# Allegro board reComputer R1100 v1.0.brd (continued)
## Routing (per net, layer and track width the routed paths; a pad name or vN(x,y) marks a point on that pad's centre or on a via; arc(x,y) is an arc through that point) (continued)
GND_ISO: length 151.2
  TOP w1.016: J23.5 98.62,20.46 R165.1 97.77,19.8 v1(92.81,14.85) v1(92.38,14.41) v1(91.95,13.98) v1(91.52,13.55)
  LYR2_GND w0.375: J21.6 81.09,8.56 ; J21.6 79.83,7.3 ; J21.6 81.09,6.04 ; J21.6 82.34,7.3 ; 102.69,7.3 J21.18 ; J21.18 103.95,8.56 ; J21.18 103.95,6.04 ; J21.18 105.2,7.3 ; 103.95,9.54 J21.17 ; J21.17 105.2,10.8 ; J21.17 102.69,10.8 ; J21.17 103.95,12.06 ; J21.5 81.09,12.06 ; J21.5 81.09,9.54 ; J21.5 79.83,10.8 ; J21.5 82.34,10.8 ; 59.04,19.26 U22.3 59.75,18.3
  LYR3 w0.375: 81.09,6.04 J21.6 ; J21.6 81.09,8.56 ; J21.6 82.34,7.3 ; J21.6 79.83,7.3 ; 59.04,19.26 U22.3 59.75,18.3 ; 81.09,9.54 J21.5 ; J21.5 79.83,10.8 ; J21.5 82.34,10.8 ; J21.5 81.09,12.06 ; J21.17 105.2,10.8 ; J21.17 103.95,9.54 ; J21.17 102.69,10.8 ; J21.17 103.95,12.06 ; J21.18 103.95,8.56 ; J21.18 102.69,7.3 ; J21.18 105.2,7.3 ; J21.18 103.95,6.04
  LYR4_GND w0.375: 103.95,9.54 J21.17 ; J21.17 105.2,10.8 ; J21.17 103.95,12.06 ; J21.17 102.69,10.8 ; 102.69,7.3 J21.18 ; J21.18 103.95,8.56 ; J21.18 103.95,6.04 ; J21.18 105.2,7.3 ; 79.83,7.3 J21.6 ; J21.6 82.34,7.3 ; J21.6 81.09,6.04 ; J21.6 81.09,8.56 ; 59.75,18.3 U22.3 59.04,19.26 ; 81.09,9.54 J21.5 ; J21.5 81.09,12.06 ; J21.5 82.34,10.8 ; J21.5 79.83,10.8
  LYR5_PWR w0.375: 79.83,10.8 J21.5 ; J21.5 81.09,12.06 ; J21.5 82.34,10.8 ; J21.5 81.09,9.54 ; J21.6 82.34,7.3 ; J21.6 81.09,6.04 ; J21.6 81.09,8.56 ; J21.6 79.83,7.3 ; 103.95,9.54 J21.17 ; J21.17 102.69,10.8 ; J21.17 105.2,10.8 ; J21.17 103.95,12.06 ; 102.69,7.3 J21.18 ; J21.18 103.95,8.56 ; J21.18 105.2,7.3 ; J21.18 103.95,6.04 ; 59.04,19.26 U22.3 59.75,18.3
  LYR6 w0.375: 102.69,7.3 J21.18 ; J21.18 103.95,6.04 ; J21.18 105.2,7.3 ; J21.18 103.95,8.56 ; 79.83,7.3 J21.6 ; J21.6 81.09,6.04 ; J21.6 82.34,7.3 ; J21.6 81.09,8.56 ; J21.17 103.95,12.06 ; J21.17 102.69,10.8 ; J21.17 103.95,9.54 ; J21.17 105.2,10.8 ; J21.5 82.34,10.8 ; J21.5 79.83,10.8 ; J21.5 81.09,9.54 ; J21.5 81.09,12.06
  LYR7_GND w0.375: 79.83,10.8 J21.5 ; J21.5 81.09,9.54 ; J21.5 81.09,12.06 ; J21.5 82.34,10.8 ; J21.18 103.95,8.56 ; J21.18 105.2,7.3 ; J21.18 103.95,6.04 ; J21.18 102.69,7.3 ; 103.95,9.54 J21.17 ; J21.17 103.95,12.06 ; J21.17 102.69,10.8 ; J21.17 105.2,10.8 ; 59.04,19.26 U22.3 59.75,18.3 ; J21.6 82.34,7.3 ; J21.6 81.09,6.04 ; J21.6 79.83,7.3 ; J21.6 81.09,8.56
  BOTTOM w1.524: C134.2 78.87,15.61 D34.1 81.09,13.4 J21.5 J21.6
  vias: v1(57.69,21.93) v1(57.71,21.47) v1(57.71,21.02) v1(57.69,20.56)
GND_ISO_DI: length 11
  BOTTOM w1.016: J21.11 92.52,13.11 94.81,15.4 J20.1 J20.2 100.24,15.4
V3: length 2.2
  TOP w0.254: U15.6 36.64,51.47 C101.2 R91.2
VCC_USB1:
  vias: v1(98.45,54.52) v1(98.45,54.06) v1(98.99,54.52) v1(99.01,54.06) v1(108.94,74.99) v1(108.94,74.56) v1(109.37,74.99) v1(109.37,74.56)
VCC_USB2:
  vias: v1(101.35,52.62) v1(101.35,52.18) v1(101.86,52.62) v1(101.86,52.18) v1(111.91,70.45) v1(111.94,70.01) v1(112.37,70.45) v1(112.4,70.01)
VDD18CORE: length 20.7
  TOP w0.254: C14.1 44.95,34.06 v1(45.53,33.48) U4.38 ; U4.15 57.28,35.48 C19.1 58.47,36.09 C6.1 v1(58.77,36.83)
  LYR6 w0.305: v1(45.53,33.48) 46.97,34.91 56.85,34.91 v1(58.77,36.83)
VDD18ETHPLL: length 3.3
  TOP w0.254: FB3.1 43.36,28.14 C502.1 44.67,28.48 U4.48
VDD18USBPLL: length 14.2
  TOP w0.254: v1(52.96,28.76) 53.34,28.39 U4.62
  TOP w0.305: FB3.2 C501.1 43.41,25.26 43.72,25.56 v1(43.72,25.74)
  LYR6 w0.381: v1(52.96,28.76) 52.33,29.4 47.37,29.4 v1(43.72,25.74)
VDD33_HUB1: length 51.7
  TOP w0.254: C46.1 44.85,32.75 44.34,32.24 R43.1 ; C46.1 44.91,32.98 U4.39 ; C46.1 v1(44.85,33.49) ; v1(50.75,25.39) 50.68,25.46 R78.1 ; U4.27 49.34,37.16 48.48,38.02 46.97,38.02 v1(46.81,38.18) ; v1(44.83,29.93) 44.85,29.91 C45.1 44.93,29.48 U4.46 ; C41.1 44.79,35.98 U4.33 ; R41.1 57.25,33.77 57.98,33.05 R44.1 v1(58.24,32.68) ; R81.1 48.04,25.39 v1(47.91,25.26) ; C47.1 56.44,36.6 v1(56.37,36.68) 56.37,36.86 55.83,37.39 53.57,37.39 53.34,37.16 U4.19 ; v1(49.13,25.28) 49,25.41 R80.1 R79.1
  LYR6 w0.381: v1(47.91,25.26) 49.1,25.26 v1(49.13,25.28) 50.65,25.28 v1(50.75,25.39) 50.75,25.13 51.26,24.62 56.42,24.62 58.85,27.06 v1(58.85,28.82)
  BOTTOM w0.203: C40.1 46.54,38.01 46.01,37.49 R50.2
  BOTTOM w0.254: C40.1 v1(46.81,38.18)
  BOTTOM w0.305: v1(44.07,36.26) 43.82,36 43.81,36 42.48,36 40.54,37.93 29.77,37.93 28.72,36.88 C500.1 28.73,36.65 U33.8
  vias: v1(44.07,36.71) v1(44.5,36.71) v1(44.5,36.26) v1(58.42,28.82)
VDD33_HUB2: length 102.9
  TOP w0.254: v1(77.11,74.63) 77.9,73.84 v1(77.9,68.54) ; U4.40 v1(46.81,32.48)
  TOP w0.305: v1(97.26,74.43) R66.2 R61.2 R67.2 R62.2 R68.2 ; U5.5 v1(102.36,69.45) ; C64.1 94.82,65.85 v1(94.8,65.87) 94.13,66.53 94.13,69.02 94.57,69.45 U5.23 ; C63.1 96.88,65.54 v1(96.9,65.57) U5.29 ; U5.10 v1(100.4,72.95) ; v1(100.51,65.87) 100.51,66.2 100.4,66.31 U5.36 ; R65.2 R60.2 98.69,74.06 98.18,73.55 C67.1 97.92,73.22 v1(97.9,73.21) U5.15
  LYR3 w0.254: v1(48.69,65.34) 48.69,52.29 52.71,48.27 52.71,36.26 51.39,34.94 47.75,34.94 46.84,34.02 46.81,34.02 v1(46.81,32.48)
  BOTTOM w0.254: v1(77.9,68.54) 77.42,68.06 62.72,68.06 62.36,67.7 49.91,67.7 48.69,66.48 v1(48.69,65.34)
  BOTTOM w0.305: v1(83.19,74.08) R52.1 R59.1 ; R63.2 86.58,74.48 C73.1 v1(86.07,74.49) ; R51.1 76.57,74.09 v1(77.11,74.63) C68.1 U6.4 ; C65.1 v1(102.36,69.45) ; C62.1 100.4,71.89 v1(100.4,72.95) ; v1(100.51,65.87) 100.54,65.9 100.61,65.9 100.97,66.26 C66.1
  vias: v1(101.37,73.16) v1(101.81,73.16) v1(102.24,73.16)
VDD33A_HUB1: length 10.5
  TOP w0.254: v1(51.49,25.23) 51.33,25.39 51.33,25.59 C50.1 51.33,26.23 50.84,26.72 U4.57 ; U4.51 v1(47.84,28.47) ; C54.1 v1(56.42,30.5) 56.39,30.48 U4.5 ; v1(45.44,25.79) 45.87,26.22 C53.1 46.21,26.56 46.84,27.19 U4.49 ; U4.54 v1(49.34,28.56) ; 56.46,26.19 C52.1 ; U4.10 v1(56.36,32.98) 56.43,33.04 C51.1
  vias: v1(56.9,28.66) v1(57.33,28.71)
VDD_3.3V: length 29.7
  BOTTOM w0.203: C4.1 71.12,25.21
  BOTTOM w0.508: FB15.2 77.78,22.9 80.06,25.18 R164.1 ; 71.12,25.21 71.07,25.26
  BOTTOM w1.016: FB15.2 74.83,22.9 72.47,25.26 67.59,25.26 65.36,23.02 J17.2
VDD_3V3_PCIE: length 11.3
  LYR6 w0.381: v1(24.89,48.32) 19.28,48.32 v1(18.7,48.91)
  BOTTOM w0.254: C168.1 25.01,47.93 25.53,47.41 R175.1
  BOTTOM w0.305: OSC1.1 OSC1.4 23.73,47.93 C168.1 v1(24.89,48.32)
  vias: v1(17.76,49.34) v1(18.21,49.34) v1(18.21,48.91) v1(18.7,49.34) v1(19.46,69.84) v1(19.46,69.4) v1(19.46,68.97) v1(19.46,67.19) v1(19.46,66.76) v1(19.46,66.33) v1(19.46,65.9)
VDD_3V3_SYS: length 68.9
  TOP w0.203: U3.9 60.28,28.27 C38.1
  TOP w0.254: 36.98,63.39 C508.1 v1(36.67,64.01) ; 36.98,63.39 37.18,63.19 U20.7 ; 36.98,63.39 36.68,63.09 U20.8 ; v1(66.04,36.64) 66.04,36.59 65.83,36.37 R654.1 ; U19.8 v1(33.65,70.13)
  TOP w0.305: v1(33.65,70.13) 33.63,70.11 C110.2 ; v1(61.04,28.43) 61.04,28.29 60.73,27.99 C38.1 ; R128.1 v1(17.61,63.79) ; R85.1 R88.1 R89.1 24.98,72.14 24.48,71.63 24.48,70.37 ; v1(16.94,62.32) 17.11,62.15 R127.1 ; R124.1 17.11,54.27 v1(17.11,55.35) R125.1 ; R126.1 v1(17.11,58.75) ; v1(18.01,66.43) 17.65,66.43 R86.1
  TOP w0.381: 16.12,51.69 C129.2 v1(16.33,50.99) v1(16.33,50.56)
  TOP w0.508: D27.1 v1(10.51,75.99) ; 16.12,51.69 D40.2 13.57,52.39 13.06,52.9 13.06,57.44 13.49,57.87 J26.4
  LYR6 w0.305: v1(46.61,39.53) 49.38,39.53 50.57,40.73 58.7,40.73 61.39,43.42 v1(61.39,44.72)
  BOTTOM w0.254: U24.8 76.58,19.85 76.84,20.1 ; 61.27,47.31 61.39,47.18 v1(61.39,44.72) ; 76.84,20.1 76.81,20.1 76.57,20.35 U24.7 ; 76.84,20.1 C509.1
  BOTTOM w0.305: C30.1 46.93,39.22 v1(46.61,39.53) 46.15,39.99 R653.1 ; R102.1 60.12,79.4 60.63,79.91 C107.1 v1(60.63,80.43) 60.63,81.06 60.95,81.38 U17.8 ; C106.1 v1(16.85,20.28)
  BOTTOM w0.381: v1(40.57,29.25) 40.14,29.68 D25.1 ; C509.1 77.27,20.1 v1(78.06,20.89)
  BOTTOM w0.508: FB9.1 35,18.83 v1(34.95,18.78) ; R38.1 v1(16.77,76.49)
  BOTTOM w0.635: J13.7 17.35,15.02 17.91,15.58 17.91,18.22 17.3,18.83 J13.1
  vias: v1(13.06,46.85) v1(13.06,46.39) v1(13.49,46.85) v1(13.49,46.39) v1(13.92,46.85) v1(13.92,46.39) v1(15.78,5.9) v1(15.78,5.42) v1(17.27,20.28) v1(23.37,70.73) v1(23.83,70.7) v1(40.54,28.82) v1(41.07,29.25) v1(41.07,28.82) v1(42.9,31.97) v1(42.9,31.53) v1(43.33,31.97) v1(43.33,31.53) v1(60.89,49.58) v1(60.89,49.1) v1(60.89,48.67) v1(60.89,48.21) v1(61.34,49.58) v1(61.34,49.1) v1(61.34,48.67) v1(61.34,48.21) v1(64.52,27.55) v1(64.52,27.11) v1(75.01,25.6) v1(75.01,25.14) v1(75.44,25.6) v1(75.44,25.14) v1(103.02,75.53) v1(103.02,75.09) v1(103.28,74.71) v1(103.79,74.71)
VDD_5V_SYS: length 32.8
  LYR6 w0.305: v1(64.75,37.88) 65.05,38.19 70.67,38.19 73,40.52 76.94,40.52 81.13,44.72 v1(81.13,47.89)
  BOTTOM w0.254: 9.73,36.41 9.72,36.4 R33.2
  BOTTOM w0.305: R104.1 11.26,72.83 R105.1 13.9,72.71 14.33,72.27 16.41,72.27 16.88,72.74 U18.5 17.61,72.74 17.88,73 C108.1 v1(18.44,73) ; C17.1 63.89,38.49 R652.1 63.9,38.43 64.42,37.91 64.62,37.91 64.72,37.91 v1(64.75,37.88)
  vias: v1(5.62,38.82) v1(5.62,38.32) v1(6.12,38.82) v1(6.12,38.32) v1(17.05,73.34) v1(17.5,73.37) v1(52.02,78.14) v1(52.02,77.71) v1(52.02,77.28) v1(52.45,78.14) v1(52.45,77.71) v1(52.45,77.28) v1(52.89,78.14) v1(52.89,77.71) v1(76.84,24.57) v1(77.27,24.57) v1(77.7,24.57) v1(80.62,49.29) v1(80.62,48.83) v1(80.62,48.35) v1(80.65,47.89) v1(80.93,67.55) v1(80.95,67.07) v1(81.13,49.29) v1(81.13,48.83) v1(81.13,48.35) v1(81.38,67.55) v1(81.41,67.07) v1(81.84,67.55) v1(81.87,67.07) v1(82.2,56.43) v1(82.2,55.92) v1(82.3,67.55) v1(82.32,67.07) v1(82.7,56.4) v1(82.7,55.89) v1(83.21,56.43) v1(83.21,55.92) v1(83.67,56.43) v1(83.67,55.92) v1(100.1,52.62) v1(100.1,52.18) v1(100.61,52.62) v1(100.61,52.18) v1(108.51,72.83) v1(108.51,72.33) v1(108.99,72.83) v1(108.99,72.33)
VDD_IN:
  vias: v1(17.53,81.09) v1(18.04,81.09) v1(18.52,81.06) v1(18.52,80.56) v1(32.01,78.27) v1(31.98,77.79) v1(31.98,77.28) v1(42.45,53.58) v1(42.9,54.06) v1(42.9,53.58) v1(61.62,40.4) v1(61.62,39.94) v1(61.62,39.48) v1(62.05,40.4) v1(62.05,39.94) v1(62.05,39.48) v1(62.49,40.4) v1(62.49,39.94) v1(62.49,39.48) v1(64.09,53.56) v1(64.59,53.56) v1(70.59,30.36) v1(70.59,29.91) v1(70.59,29.45) v1(70.59,28.99) v1(71.05,30.36) v1(71.05,29.91) v1(71.05,29.45) v1(71.05,28.99) v1(82.25,38.77) v1(82.25,38.32) v1(82.25,37.86) v1(82.68,38.77) v1(82.68,38.32) v1(82.68,37.86) v1(83.11,38.77) v1(83.11,38.32) v1(83.11,37.86)
VDD_LTE_3V3: length 7
  BOTTOM w0.305: TP31.1 110.19,33.06 109.5,32.37 107.65,32.37 107.37,32.65 v1(107.37,33.31)
  BOTTOM w0.381: J15.41 v1(84.55,28.69) ; J15.39 v1(85.35,28.69)
  vias: v1(74.42,75.75) v1(74.98,75.75) v1(79.53,35.29) v1(79.53,34.86) v1(79.53,34.43) v1(79.53,34) v1(106.83,33.82) v1(106.83,33.31) v1(107.37,33.82)
VDD_RTC: length 11.8
  TOP w0.305: 14.15,74.03 14.19,74.07 C105.1 13.85,74.39 13.84,74.38
  TOP w0.508: 14.15,74.03 14.15,72.81 14.66,72.3 U16.8 ; v1(13.83,78.1) D29.2 D27.2 12.77,76.71 12.15,76.09 D28.2 12.15,74.38 C104.1 13.84,74.38
  BOTTOM w0.508: TP22.1 13.58,78.1 v1(13.83,78.1)
VDD_UPS: length 10.2
  BOTTOM w0.508: 85.42,45.9 84.15,44.63 Q1.5 ; 85.42,45.9 Q1.6 ; 85.42,45.9 Q1.9 85.42,47.17 ; 85.42,47.17 84.15,48.44 Q1.8 ; 85.42,47.17 Q1.7
  vias: v1(82.68,43.12) v1(82.68,42.66) v1(82.68,42.2) v1(82.68,41.72) v1(83.14,43.12) v1(83.14,42.66) v1(83.14,42.2) v1(83.14,41.72)
BUZZER_EN: length 9.7
  TOP w0.121: v1(32.01,72.15) 32.01,71.74 31.62,71.36 U12.11
  LYR6 w0.121: v1(32.01,72.15) 31.5,72.66 v1(25.1,72.66)
  BOTTOM w0.121: v1(25.1,72.66) 24.62,73.14 R39.1
CAM0_C_N: length 76.2
  TOP w0.095: J5.140 66.14,38.81 66.14,40.21 65.75,40.6 65.15,40.6 v1(65.04,40.72)
  LYR6 w0.102: v1(65.04,40.72) 65.14,40.61 65.6,40.61 65.99,41 65.99,43.14 63.83,45.3 50.9,45.3 47.62,48.58 28.35,48.58 24.56,52.36 13.34,52.36 9.99,55.71 9.99,58.36 10.27,58.64 10.78,58.64 10.88,58.74 v1(10.88,59.03)
  BOTTOM w0.095: D58.2 10.92,59.07 v1(10.88,59.03) 10.76,58.91 9.77,58.91 9.65,59.04 J24.8
CAM0_C_P: length 76.4
  TOP w0.095: v1(65.04,40.21) 65.15,40.32 65.64,40.32 65.86,40.1 65.86,39.93 65.77,39.84 65.6,39.84 65.51,39.74 65.51,39.55 65.6,39.46 65.77,39.46 65.86,39.36 65.86,38.81 J5.142
  LYR6 w0.102: v1(65.04,40.21) 65.14,40.31 65.73,40.31 66.3,40.88 66.3,43.27 63.96,45.6 51.03,45.6 47.75,48.88 28.48,48.88 24.69,52.67 13.46,52.67 10.29,55.84 10.29,58.23 10.4,58.34 10.78,58.34 10.88,58.24 10.88,57.95 v1(10.91,57.95)
  BOTTOM w0.095: D59.2 10.93,57.93 v1(10.91,57.95) 10.23,58.64 9.92,58.64 9.77,58.49 9.77,58.25 9.54,58.03 8.19,58.03 8.04,58.18 8.04,58.44 8.14,58.54 J24.9
CAM0_D0_N: length 87.3
  TOP w0.095: J5.128 68.54,38.81 68.54,39.68 68.18,40.03 v1(68.18,40.2)
  LYR6 w0.102: v1(68.18,40.2) 68.18,40.05 68.4,39.84 68.73,39.84 68.84,39.94 68.84,41.72 68.05,42.51 68.05,44.31 65.33,47.03 52,47.03 46.87,52.16 35.79,52.16 35.17,51.54 28.56,51.54 25.57,54.53 19.73,54.53 19.63,54.43 19.63,54.29 19.53,54.19 19.32,54.19 19.22,54.29 19.22,54.43 19.12,54.53 18.92,54.53 18.82,54.43 18.82,54.34 18.71,54.24 18.51,54.24 18.41,54.34 18.41,54.43 18.31,54.53 18.1,54.53 18,54.43 18,54.34 17.9,54.24 17.7,54.24 17.6,54.34 17.6,54.43 17.5,54.53 17.29,54.53 17.19,54.43 17.19,54.34 17.09,54.24 16.89,54.24 16.78,54.34 16.78,54.43 16.68,54.53 16.48,54.53 16.38,54.43 16.38,54.34 16.28,54.24 16.07,54.24 15.97,54.34 15.97,54.43 15.87,54.53 15.67,54.53 15.56,54.43 15.56,54.34 15.46,54.24 15.26,54.24 15.16,54.34 15.16,54.43 15.06,54.53 14.59,54.53 13.1,56.03 13.1,62.48 11.15,64.43 10.54,64.43 10.26,64.15 10.26,63.05 10.44,62.88 10.71,62.88 10.81,62.98 v1(10.81,63.28)
  BOTTOM w0.095: J24.2 6.57,62.04 9.57,62.04 v1(10.81,63.28) 10.84,63.31 D53.2
CAM0_D0_P: length 87.2
  TOP w0.095: J5.130 68.26,38.81 68.26,39.56 67.99,39.84 v1(67.83,39.84)
  LYR6 w0.102: v1(10.81,62.17) 10.81,62.47 10.71,62.57 10.32,62.57 9.96,62.93 9.96,64.27 10.42,64.73 11.28,64.73 13.4,62.61 13.4,56.16 14.72,54.84 25.69,54.84 28.69,51.84 35.04,51.84 35.66,52.46 46.99,52.46 52.12,47.33 65.46,47.33 68.35,44.44 68.35,42.63 69.14,41.85 69.14,39.81 68.86,39.53 68.27,39.53 67.97,39.84 v1(67.83,39.84)
  BOTTOM w0.095: D55.2 10.82,62.17 v1(10.81,62.17) 10.6,62.38 10.3,62.38 9.74,61.82 9.74,61.28 9.48,61.02 8.16,61.02 8.07,61.12 8.07,61.44 8.16,61.54 J24.3
CAM0_D1_N: length 77
  TOP w0.095: J5.134 67.4,39.31 67.34,39.37 67.34,40.28 v1(67.46,40.4)
  LYR6 w0.102: v1(67.46,40.4) 67.35,40.5 67.35,43.76 64.62,46.49 51.39,46.49 46.39,51.5 36.3,51.5 35.51,50.71 28.22,50.71 25.22,53.71 14.25,53.71 11.79,56.17 11.79,60.48 11.51,60.76 10.94,60.76 10.84,60.86 v1(10.84,61.15)
  BOTTOM w0.095: D56.2 10.87,61.18 v1(10.84,61.15) 10.84,60.57 10.72,60.45 10.52,60.45 10.4,60.57 10.4,61.22 10.29,61.33 10.15,61.33 10.05,61.23 10.05,60.51 9.95,60.41 9.74,60.41 9.62,60.54 J24.5
CAM0_D1_P: length 77.1
  TOP w0.095: v1(66.95,40.4) 67.06,40.28 67.06,39.37 67,39.31 J5.136
  LYR6 w0.102: v1(66.95,40.4) 67.05,40.5 67.05,43.63 64.49,46.19 51.27,46.19 46.26,51.19 36.43,51.19 35.64,50.41 28.09,50.41 25.1,53.4 17.49,53.4 17.33,53.25 17.08,53.25 16.93,53.4 16.67,53.4 16.52,53.25 16.27,53.25 16.12,53.4 15.86,53.4 15.71,53.25 15.45,53.25 15.3,53.4 15.05,53.4 14.9,53.25 14.64,53.25 14.49,53.4 14.12,53.4 11.48,56.04 11.48,60.35 11.38,60.45 10.94,60.45 10.84,60.35 v1(10.84,60.06)
  BOTTOM w0.095: D57.2 10.85,60.04 v1(10.84,60.06) 10.8,60.02 10.56,60.02 10.44,60.13 9.74,60.13 9.65,60.04 J24.6
CAM_GPIO: length 80
  TOP w0.121: J4.97 54.6,75.21 54.49,75.09 49.96,75.09 45.27,70.4 41.02,70.4 v1(39.52,71.89)
  LYR6 w0.121: v1(39.52,71.89) 35.27,76.15 24.09,76.15 23.95,76.29 21.82,76.29 19.69,74.15 16.87,74.15 16.18,73.47 16.18,69.35 16.06,69.23 11.58,69.23 5.16,62.8 v1(5.16,55.54)
  BOTTOM w0.121: J24.17 D64.2 11.37,55.65 10.98,56.04 7.93,56.04 7.42,55.54 v1(5.16,55.54)
CH344_RST: length 101.2
  TOP w0.121: v1(29.44,73.39) 29.68,73.16 U12.15 ; J22.2 70.86,15.63 v1(67.77,15.63)
  LYR3 w0.121: v1(29.44,73.39) 29.44,71.41 28.73,70.7 28.73,62.5 27.18,60.95 27.18,56.5 26.34,55.66 26.34,49.14 24.82,47.61 24.82,39 27.74,36.08 27.74,30.34 v1(29.87,28.21)
  LYR6 w0.121: v1(29.87,28.21) 31.45,28.21 32.9,26.76 39.32,26.76 41.43,24.65 47.88,24.65 50.07,22.47 56.59,22.47 59.18,25.06 62.37,25.06 62.49,24.94 62.49,24.01 63.4,23.1 63.4,20 v1(67.77,15.63)
CM4_GPIO16: length 74.1
  TOP w0.121: J4.29 v1(68.2,75.2)
  LYR3 w0.121: v1(66.96,17.54) 65.74,17.54 61.62,21.65 61.62,23.91 61.45,24.09 61.45,27.16 62.99,28.71 64.44,28.71 70.84,35.11 70.84,36.71 71.81,37.68 71.81,38.19 73.79,40.17 73.79,42.66 74.37,43.24 74.37,43.85 70.16,48.07 70.16,61.18 68.76,62.57 68.76,65.57 68.07,66.26 68.07,66.99 68.25,67.17 68.25,70.42 67.82,70.85 67.82,74.27 68.2,74.65 v1(68.2,75.2)
  BOTTOM w0.121: J17.8 65.15,15.4 66.96,17.21 v1(66.96,17.54)
CM4_GPIO17: length 70.4
  TOP w0.121: J4.50 v1(64.2,72.1)
  LYR3 w0.121: v1(71.07,66.23) 71.94,65.37 71.94,48.93 76.76,44.11 76.76,29.45 68.25,20.94 68.25,20.2 67.52,19.47 v1(67.52,17.79) ; v1(64.2,72.1) 64.2,68.83 65.28,67.75 65.28,67.58 v1(65.28,67.58)
  BOTTOM w0.121: v1(67.52,17.79) 67.52,16.78 68.89,15.4 J17.7 ; v1(71.07,66.23) 69.73,67.58 v1(65.28,67.58)
CM4_GPIO_VREF: length 43.6
  TOP w0.203: J4.78 v1(58.6,72.07)
  TOP w0.305: v1(61.34,80.71) 61.66,80.39 R106.1 R107.1 R178.1 R177.1 ; R30.1 R31.1 v1(35.76,68.74)
  LYR3 w0.305: v1(61.34,80.71) 61.34,80.35 59.54,78.55 v1(59.54,73.42)
  BOTTOM w0.305: C35.2 58.76,72.78 R29.1 ; C35.2 58.88,72.35 v1(58.6,72.07) 57.81,71.28 48.06,71.28 46.32,69.55 36.57,69.55 v1(35.76,68.74) ; C35.2 59.03,72.9 v1(59.54,73.42) 60.3,74.18 TP16.1
CM4_IIC0_SCL: length 96
  TOP w0.121: R177.2 66.84,79.66 v1(66.7,79.51) ; v1(67.36,76.49) 67,76.13 J4.35
  LYR3 w0.121: v1(67.36,76.49) 67,76.85 67,77.94 66.7,78.24 v1(66.7,79.51)
  LYR6 w0.121: v1(66.7,79.51) 66.7,79.37 65.65,78.32 59.09,78.32 58.35,77.58 54.41,77.58 51.47,74.64 50.7,74.64 45.65,69.58 38.66,69.58 33.86,74.38 24.25,74.38 21.54,71.67 18.45,71.67 18.04,71.26 18.04,68.9 17.5,68.36 11.79,68.36 5.97,62.55 5.97,54.29 6.86,53.4 10.43,53.4 v1(10.51,53.49)
  BOTTOM w0.121: D60.2 10.51,53.49 v1(10.51,53.49) 10.06,53.04 J24.20
CM4_IIC0_SDA: length 97.1
  TOP w0.121: J4.36 v1(67,73.29) ; R178.2 v1(66.08,79.32)
  LYR3 w0.121: v1(67,73.29) 67,74.24 66.27,74.97 66.27,77.99 66.08,78.18 v1(66.08,79.32)
  LYR6 w0.121: v1(66.08,79.32) 65.36,78.6 59.02,78.6 58.25,77.82 54.31,77.82 51.44,74.96 50.56,74.96 45.44,69.84 38.75,69.84 33.96,74.62 24.15,74.62 21.52,72 18.21,72 17.68,71.46 17.68,69.07 17.3,68.69 11.61,68.69 5.62,62.7 5.62,54.14 7.22,52.54 v1(10.55,52.54)
  BOTTOM w0.121: D54.2 10.62,52.47 v1(10.55,52.54) J24.21
CM4_IIC1_SCL: length 8.1
  TOP w0.121: R30.2 36.48,67.71 v1(36.63,67.71) 36.92,67.71 R27.1 ; v1(33.58,71.54) 33.99,71.13 U19.6
  LYR3 w0.121: v1(33.58,71.54) 34.03,71.09 34.03,69.1 35.43,67.71 v1(36.63,67.71)
CM4_IIC1_SDA: length 7
  TOP w0.121: U19.5 34.25,71.63 v1(34.04,71.84) ; R31.2 v1(36.61,68.3) R28.1
  LYR3 w0.121: v1(36.61,68.3) 35.28,68.3 34.5,69.07 34.5,71.39 v1(34.04,71.84)
CM4_IIC3_SCL: length 119.5
  TOP w0.121: v1(37.14,65.14) 37.13,65.15 R24.1 ; U12.19 27.47,71.86 v1(27.07,72.26) 26.5,72.83 R88.2 ; v1(69.73,18.99) 69.73,18.12 69.93,17.92 J22.4
  LYR3 w0.121: v1(27.05,65.14) 27.05,67.47 26.95,67.58 26.95,72.15 v1(27.07,72.26) ; v1(50.5,24.62) 50.12,25.01 50.12,32.42 50.51,32.81 53.86,32.81 57.28,36.23 v1(57.28,36.86) 56.81,36.86 56.37,37.3 56.37,52.01 55.65,52.72 55.65,66.1 v1(55.25,66.51)
  LYR6 w0.121: v1(50.5,24.62) 50.22,24.35 50.22,23.68 50.6,23.29 56.23,23.29 59.68,26.75 65.23,26.75 65.28,26.7 65.58,26.7 65.63,26.75 67.98,26.75 69.73,25.01 v1(69.73,18.99) ; v1(27.05,65.14) v1(37.14,65.14) 37.9,65.9 54.64,65.9 v1(55.25,66.51)
  BOTTOM w0.121: J14.30 56.84,36.42 v1(57.28,36.86)
CM4_IIC3_SDA: length 116.4
  TOP w0.121: J22.6 69.58,20.46 69.33,20.7 v1(69.33,21.37) ; U12.20 27.08,71.36 v1(26.55,71.89) 26.3,72.14 R89.2 ; v1(36.55,65.54) 36.55,66.13 R25.1
  LYR3 w0.121: v1(26.55,71.89) v1(26.55,65.54) ; v1(54.18,66.97) 55.4,65.75 55.4,52.62 56.11,51.9 56.11,37.07 55.76,36.71 v1(55.76,36.7) 55.76,35.34 53.67,33.26 50.32,33.26 49.74,32.68 49.74,25.16 49.08,24.5 v1(49.08,24.45)
  LYR6 w0.121: v1(69.33,21.37) 69.33,24.84 67.82,26.35 59.85,26.35 56.39,22.9 50.35,22.9 49.08,24.17 v1(49.08,24.45) ; v1(26.55,65.54) v1(36.55,65.54) 37.01,65.54 37.75,66.28 53.49,66.28 v1(54.18,66.97)
  BOTTOM w0.121: J14.32 56.04,36.42 v1(55.76,36.7)
CM4_IIC5_SCL: length 110.1
  TOP w0.121: U16.6 16.89,69.76 v1(16.94,69.81) ; v1(63.27,35.39) 63.6,35.06 J2.11 ; R6.1 v1(64.62,79.29) R106.2
  LYR3 w0.121: v1(64.62,79.29) 65,78.9 65,74.51 65.46,74.05 65.46,70.9 65.89,70.47 65.89,59.22 66.96,58.15 66.96,41.72 66.19,40.96 66.19,38.59 63.43,35.83 63.43,35.55 v1(63.27,35.39)
  LYR6 w0.121: v1(16.94,69.81) 16.94,72.05 17.5,72.61 21.14,72.61 23.65,75.12 34.17,75.12 38.92,70.37 45.09,70.37 50.35,75.63 51.41,75.63 54.1,78.32 58.04,78.32 59.01,79.29 v1(64.62,79.29)
  BOTTOM w0.121: U17.6 64.18,78.84 v1(64.62,79.29)
CM4_IIC5_SDA: length 116.1
  TOP w0.121: v1(17,69.18) 16.31,68.49 U16.5 ; R107.2 v1(65.38,79.31) R1.2 ; J2.13 62.33,35.17 v1(62.56,35.39)
  LYR3 w0.121: v1(65.38,79.31) 65.37,79.3 65.37,74.66 65.74,74.29 65.74,71.11 66.19,70.65 66.19,59.27 67.95,57.52 67.95,47.41 68.85,46.51 68.85,39.54 67.46,38.16 66.19,38.16 63.73,35.7 63.73,35.3 63.44,35 62.9,35 62.56,35.34 v1(62.56,35.39)
  LYR6 w0.121: v1(17,69.18) 17.38,69.56 17.38,71.74 17.96,72.33 21.29,72.33 23.83,74.87 34.07,74.87 38.85,70.09 45.24,70.09 50.39,75.24 51.37,75.24 54.21,78.07 58.14,78.07 58.97,78.89 64.97,78.89 v1(65.38,79.31)
  BOTTOM w0.121: v1(65.38,79.31) 63.64,77.57 U17.5
CM4_IN1: length 115.6
  TOP w0.121: v1(68.23,71.11) 68.23,68.72 67.8,68.29 62.38,68.29 62,68.67 57.31,68.67 56.47,67.82 56.47,66.38 55.66,65.57 54.25,65.57 53.18,66.64 49.26,66.64 48.37,65.75 41.38,65.75 40.64,65.01 40.64,59.09 39.78,58.23 37.42,58.23 37.18,58.47 U20.2 ; J4.49 64.2,75.44 64.39,75.25 v1(64.39,75.02)
  LYR3 w0.121: v1(70.41,71.11) 70.41,66.1 71.66,64.86 71.66,48.63 75.77,44.51 75.77,29.08 67.68,21 v1(67.68,20.43) ; v1(65.23,69.63) 65.23,70.62 64.59,71.26 64.59,74.81 v1(64.39,75.02)
  BOTTOM w0.121: v1(65.23,69.63) 67.03,69.63 67.31,69.91 67.31,70.67 67.74,71.11 v1(68.23,71.11) v1(70.41,71.11) ; v1(67.68,20.43) 69.76,20.43 J17.3
CM4_IN1_LED: length 94.6
  TOP w0.121: v1(16.65,3.02) J25.7 ; v1(35.69,62.63) 35.69,62.27 36.45,61.51 37.44,61.51 37.68,61.74 U20.6
  LYR3 w0.121: v1(16.65,3.02) 16.59,3.09 12.22,3.09 11.15,4.15 11.15,10.68 7.24,14.59 7.24,21.1 5.62,22.73 5.62,26.81 6.96,28.16 6.96,41.38 8.21,42.63 13.62,42.63 22.41,51.42 22.41,60.41 22.43,60.44 v1(22.43,61.56)
  BOTTOM w0.121: v1(35.69,62.63) 35.13,62.63 33.51,61 22.55,61 22.43,61.12 v1(22.43,61.56)
CM4_IN2: length 100.1
  TOP w0.121: J4.26 69,71.58 68.99,71.56 ; 68.99,71.56 v1(69.93,71.56) ; 68.99,71.56 68.02,71.56 67.07,70.61 67.07,69.19 66.55,68.67 62.54,68.67 62.16,69.05 57.15,69.05 56.09,67.98 56.09,66.53 55.5,65.95 54.41,65.95 53.34,67.02 49.1,67.02 48.21,66.13 39.96,66.13 38.18,64.35 U20.5
  LYR3 w0.121: v1(67.06,20.43) 67.06,20.95 75.36,29.25 75.36,44.39 71.29,48.46 71.29,64.61 69.93,65.98 v1(69.93,71.56)
  BOTTOM w0.121: v1(67.06,20.43) 64.44,20.43 J17.4
CM4_IN2_LED: length 94.1
  TOP w0.121: U20.3 37.68,61.04 37.57,61.15 36.25,61.15 34.89,62.51 v1(34.28,62.51) ; v1(17.65,3.02) J25.8
  LYR3 w0.121: v1(17.65,3.02) 17.16,3.52 12.5,3.52 11.97,4.05 11.97,10.58 7.74,14.8 7.74,21.3 6.11,22.93 6.11,26.6 7.46,27.95 7.46,41.18 8.42,42.14 13.83,42.14 22.99,51.3 22.99,59.65 23.29,59.96 v1(23.29,61.45)
  BOTTOM w0.121: v1(23.29,61.45) 33.23,61.45 v1(34.28,62.51)
CM4_IO_INT: length 52.6
  TOP w0.121: U12.22 27.06,70.36 26.77,70.06 R90.2 26.37,69.84 26.24,69.71 25.55,69.71 25.12,69.28 v1(25.12,64.1) ; J4.54 v1(63.4,69.35)
  BOTTOM w0.121: v1(63.4,69.35) 62.13,69.35 61.62,68.85 48.87,68.85 45.16,65.14 40.26,65.14 38.59,63.46 34.72,63.46 33.91,64.27 25.3,64.27 v1(25.12,64.1)
CM4_OUT1: length 73.8
  TOP w0.121: J4.27 v1(68.6,74.76)
  LYR3 w0.121: v1(68.6,74.76) 68.6,73.02 69.17,72.45 69.17,62.66 70.51,61.32 70.51,48.14 74.7,43.94 74.7,29.7 66.17,21.17 v1(66.17,18.96)
  BOTTOM w0.121: U24.2 73.95,20.35 74.07,20.23 74.07,19.57 72.44,17.94 J17.5 68.58,17.94 67.57,18.96 v1(66.17,18.96)
CM4_OUT1_LED: length 7.6
  TOP w0.121: J22.8 v1(73.08,23)
  BOTTOM w0.121: v1(73.08,23) 74.27,21.81 76.49,21.81 76.71,21.58 76.71,21.2 76.36,20.85 U24.6
CM4_OUT2: length 81.8
  TOP w0.121: J4.25 v1(69,75.18)
  LYR3 w0.121: v1(66.61,19.54) 66.61,21.09 74.96,29.45 75.03,29.52 75.03,44.08 70.84,48.27 70.84,61.45 69.5,62.8 69.5,72.33 70.28,73.11 70.28,73.42 69,74.7 v1(69,75.18)
  BOTTOM w0.121: v1(66.61,19.54) 64.92,19.54 64.39,19 J17.6 64.74,18.3 67.72,18.3 67.92,18.1 67.92,17.28 68.18,17.03 72.16,17.03 74.45,19.32 74.45,21.12 74.68,21.35 U24.5
CM4_OUT2_LED: length 7.3
  TOP w0.121: J22.10 71.11,24.31 71.4,24.01 v1(72.42,24.01)
  BOTTOM w0.121: U24.3 73.59,20.85 73.84,21.09 73.84,21.58 72.42,23 v1(72.42,24.01)
CM4_SDIO_CLK: length 56.7
  TOP w0.121: R129.1 v1(17.66,60.56) ; J4.46 v1(65,73.44)
  LYR6 w0.121: v1(17.66,60.56) 17.66,62.96 20.73,66.03 24.46,66.03 26.77,68.34 34.34,68.34 35.18,69.18 36.27,69.18 37.29,68.16 51.74,68.16 54.99,71.41 61.52,71.41 63.88,73.77 64.67,73.77 v1(65,73.44)
CM4_SDIO_CMD: length 68.8
  TOP w0.121: J26.3 15.56,56.77 D39.2 16.36,57.57 R126.2 v1(17.63,57.57) ; v1(60.09,77.1) 64.36,77.1 64.6,76.86 J4.47
  LYR6 w0.121: v1(28.65,73.98) 24.36,73.98 23.01,72.63 23.01,71.97 19.43,68.39 18.14,68.39 16.23,66.48 16.23,61.05 17.63,59.65 v1(17.63,57.57)
  BOTTOM w0.121: v1(60.09,77.1) 59.31,77.1 58.85,77.56 54.26,77.56 53.14,78.68 38.9,78.68 35.24,75.02 29.42,75.02 28.65,74.26 v1(28.65,73.98)
CM4_SDIO_DATA0: length 64.7
  TOP w0.121: v1(17.11,60.93) R127.2 16.77,61.38 16.56,61.17 D42.2 16.15,61.17 J26.7 ; J4.45 65,77.02 64.52,77.51 v1(60.56,77.51)
  LYR6 w0.121: v1(27.89,73.54) 27.46,73.11 24.44,73.11 23.7,72.38 23.7,71.65 19.73,67.68 18.43,67.68 17.17,66.42 17.17,63.23 17.33,63.08 17.33,61.14 v1(17.11,60.93)
  BOTTOM w0.121: v1(27.89,73.54) 27.89,74.07 29.25,75.42 35.07,75.42 38.73,79.08 53.31,79.08 54.43,77.96 59.02,77.96 59.48,77.51 v1(60.56,77.51)
CM4_SDIO_DATA1: length 64.8
  TOP w0.121: v1(60.1,77.91) 64.85,77.91 65.8,76.96 J4.41 ; J26.8 15.35,62.27 D43.2 16.36,63.28 R128.2 17.11,63.17 v1(16.74,62.8)
  LYR6 w0.121: v1(27.26,73.54) 24.34,73.54 23.37,72.58 23.37,71.82 19.59,68.03 18.29,68.03 16.74,66.48 v1(16.74,62.8)
  BOTTOM w0.121: v1(27.26,73.54) 27.26,74.01 29.08,75.83 34.9,75.83 38.56,79.49 53.48,79.49 54.59,78.37 59.19,78.37 59.65,77.91 v1(60.1,77.91)
CM4_SDIO_DATA2: length 69.3
  TOP w0.121: v1(18.37,55.23) 18.37,54.42 17.71,53.76 R124.2 16.36,53.76 D37.2 15.13,54.57 J26.1 ; J4.24 v1(69.4,73.29)
  LYR6 w0.121: v1(69.4,73.29) 69.34,73.29 68.56,72.5 63.93,72.5 62.05,70.62 55.32,70.62 52.07,67.37 37.29,67.37 36.91,66.99 33.25,66.99 32.77,67.47 27.13,67.47 24.82,65.16 20.93,65.16 18.37,62.6 v1(18.37,55.23)
CM4_SDIO_DATA3: length 62.4
  TOP w0.121: J26.2 15.44,55.67 D38.2 16.95,56.38 R125.2 17.26,56.07 v1(17.73,56.07) ; J4.48 64.6,73.03 64.26,73.37 v1(64.21,73.37)
  LYR6 w0.121: v1(17.73,56.07) 18.06,56.4 18.06,62.8 20.81,65.54 24.66,65.54 26.97,67.86 32.93,67.86 33.46,67.32 36.83,67.32 37.26,67.75 51.91,67.75 55.16,71 61.75,71 64.11,73.37 v1(64.21,73.37)
CM4_SPI0_CE0: length 106.7
  TOP w0.121: J4.39 66.2,74.42 65.92,74.13 50.12,74.13 49.51,73.52 v1(49.51,72.53)
  LYR3 w0.121: v1(39.42,20.13) 39.42,21.93 40.01,22.52 40.01,24.59 39.46,25.14 39.46,26.99 34.95,31.49 34.95,44.25 43.87,53.17 43.87,66.26 49.51,71.89 v1(49.51,72.53)
  LYR6 w0.121: v1(39.42,20.13) 35.66,20.13 34.78,19.24 32.11,19.24 28.5,15.63 22.28,15.63 v1(20.12,13.47)
  BOTTOM w0.121: J13.9 19.84,13.75 v1(20.12,13.47)
CM4_SPI0_CE1: length 82.8
  TOP w0.121: J4.37 66.6,74.41 66.07,73.88 53.48,73.88 v1(53.27,73.67)
  LYR3 w0.121: v1(53.27,73.67) 53.27,69.2 51.59,67.53 47.45,67.53 45.67,65.75 45.67,51.88 37.67,43.88 37.67,41.75 36.65,40.74 36.65,31.94 41.33,27.27 41.33,25.84 41.84,25.34 v1(41.94,25.34)
  BOTTOM w0.121: J14.51 48.44,25.97 48.26,25.79 46.33,25.79 45.87,25.34 v1(41.94,25.34)
CM4_SPI0_MISO: length 118.6
  TOP w0.121: J4.40 v1(66.2,72.1)
  LYR3 w0.121: v1(42.32,21.04) 42.32,24.32 41.05,25.59 41.05,27.2 36.4,31.84 36.4,40.84 37.39,41.83 37.39,43.96 45.39,51.96 45.39,65.82 47.4,67.83 51.31,67.83 52.83,69.35 52.83,70.75 v1(52.81,70.78)
  LYR6 w0.121: v1(42.32,21.04) 42.32,20.31 39.95,17.94 31.9,17.94 28.55,14.59 22.63,14.59 20.53,12.48 v1(19.03,12.48)
  BOTTOM w0.121: v1(52.81,70.78) 57.89,70.78 58.75,71.64 65.74,71.64 v1(66.2,72.1) ; v1(42.32,21.04) 42.32,22.85 44.02,24.55 48.47,24.55 48.81,24.89 49.36,24.89 50.04,25.58 J14.47 ; J13.11 v1(19.03,12.48)
CM4_SPI0_MOSI: length 121.1
  TOP w0.121: v1(64.62,70.62) 64.62,71.11 65.4,71.89 J4.44
  LYR3 w0.121: v1(52.28,69.66) 50.8,68.19 47.35,68.19 45.09,65.92 45.09,52.12 37.14,44.17 37.14,42.05 36.07,40.98 36.07,31.81 40.77,27.11 40.77,25.46 41.7,24.54 v1(41.7,21.04)
  LYR6 w0.121: v1(41.7,21.04) 41.7,20.19 39.8,18.3 31.65,18.3 28.48,15.12 22.48,15.12 20.42,13.07 v1(18.67,13.07)
  BOTTOM w0.121: v1(18.67,13.07) 13.69,13.07 13.11,12.48 J13.12 ; v1(41.7,21.04) 41.7,23.75 42.82,24.87 48.16,24.87 49.24,25.95 J14.49 ; v1(52.28,69.66) 52.38,69.76 58.24,69.76 59.11,70.62 v1(64.62,70.62)
CM4_SPI0_SCLK: length 120.6
  TOP w0.121: v1(66.47,71.16) 66.6,71.28 J4.38
  LYR3 w0.121: v1(41.28,20.64) 41.28,20.84 41.18,20.94 41.18,24.68 40.49,25.36 40.49,27.01 35.82,31.69 35.82,41.09 36.88,42.15 36.88,44.27 44.73,52.12 44.73,65.92 47.28,68.46 50.37,68.46 v1(51.56,69.66)
  LYR6 w0.121: v1(21.85,16.01) 28.43,16.01 32.06,19.65 34.72,19.65 35.71,20.64 v1(41.28,20.64)
  BOTTOM w0.121: v1(66.47,71.16) 59.16,71.16 58.09,70.09 52,70.09 v1(51.56,69.66) ; J13.10 13.52,13.75 14.1,14.34 20.17,14.34 v1(21.85,16.01) ; R111.1 47.36,23.62 46.81,24.17 44.2,24.17 42.95,22.92 42.95,21.02 42.57,20.64 v1(41.28,20.64)
CM4_TPM_IRQ: length 113.1
  TOP w0.121: v1(67.77,74.74) 67.77,74.1 67.4,73.74 J4.34
  LYR3 w0.121: v1(10.42,18.83) 10.42,20.03 7.11,23.33 7.11,26.19 7.86,26.93 7.86,26.95 8.45,27.54 8.45,37.34 9.35,38.24 12.25,38.24 13,38.99 13,39.88 24.38,51.26 24.38,66.26 v1(23.93,66.71)
  LYR6 w0.121: v1(23.93,66.71) 24.56,66.71 29.11,71.26 32.18,71.26 33.2,72.27 34.9,72.27 38.38,68.8 46.89,68.8 53.7,75.6 67.59,75.6 67.8,75.4 67.8,74.76 v1(67.77,74.74)
  BOTTOM w0.121: J13.2 v1(10.42,18.83)
CM4_UART0_RXD: length 48.6
  TOP w0.121: J4.51 63.8,75.15 v1(63.86,75.09) ; v1(33,54.37) 33.29,54.07 R100.2
  LYR3 w0.121: v1(34.98,60.9) 35.31,60.56 35.31,58.1 33,55.79 v1(33,54.37)
  LYR3 w0.127: v1(63.86,75.09) 63.8,75.04 63.8,67.53 v1(63.81,67.53)
  BOTTOM w0.121: v1(63.81,67.53) 63.35,67.07 56.82,67.07 54.13,64.38 40.89,64.38 37,60.49 35.41,60.49 35,60.9 v1(34.98,60.9)
CM4_UART0_TXD: length 50.9
  TOP w0.121: D26.2 32.45,52.34 v1(33.3,52.34) 33.53,52.56 R99.2 ; J4.55 v1(63,75.09)
  LYR3 w0.121: v1(33.3,52.34) 32.99,52.65 32.99,53.57 33.41,53.99 33.41,55.84 35.77,58.2 v1(35.77,60.9)
  LYR3 w0.127: v1(63,75.09) v1(63,67.53)
  BOTTOM w0.121: v1(63,67.53) 62.8,67.32 56.62,67.32 53.93,64.63 40.69,64.63 36.96,60.9 v1(35.77,60.9)
CM4_UPS_DET: length 51.9
  TOP w0.121: J4.30 68.2,72.15 v1(66.6,70.55) ; J2.12 63.08,29.45 61.65,30.87 61.65,35.14 62.56,36.05 64.62,36.05 v1(64.65,36.03) 64.69,35.99 R654.2
  LYR3 w0.121: v1(64.65,36.03) 66.4,37.78 67.57,37.78 69.12,39.33 69.12,46.77 68.35,47.54 68.35,57.64 66.5,59.5 66.5,67.4 66.6,67.5 v1(66.6,70.55)
EECLK: length 17.6
  TOP w0.121: U4.23 v1(51.34,37.27)
  LYR3 w0.121: v1(37.09,35.67) 37.44,35.67 38.08,36.31 40.77,36.31 41.86,37.4 46.28,37.4 46.76,36.92 50.98,36.92 v1(51.34,37.27)
  BOTTOM w0.121: v1(37.09,35.67) 36.79,35.38 U33.2
EECS: length 18.5
  TOP w0.121: v1(50.35,38.04) 50.35,37.96 50.84,37.47 U4.24
  LYR3 w0.121: v1(37.11,37.17) 37.16,37.17 37.77,36.56 40.66,36.56 41.8,37.71 45.01,37.71 45.85,38.54 47.76,38.54 48.69,37.6 49.91,37.6 v1(50.35,38.04)
  BOTTOM w0.121: v1(37.11,37.17) 36.99,37.05 R573.1 U33.1
EEDI: length 23.6
  TOP w0.121: v1(49.1,38.06) 49.1,38.01 49.84,37.27 U4.26
  LYR3 w0.121: v1(37.62,37.38) 37.62,37.27 38.05,36.84 40.54,36.84 41.68,37.98 44.94,37.98 45.75,38.8 48.36,38.8 v1(49.1,38.06)
  BOTTOM w0.121: v1(37.62,37.38) 37.43,37.56 34.96,37.56 34.14,36.74 34.14,33.08 34.38,32.84 U33.4
EEDO: length 23
  TOP w0.121: v1(49.71,38.04) 50.34,37.41 U4.25
  LYR3 w0.121: v1(49.71,38.04) 50.24,38.57 51.03,38.57 51.74,37.86 51.74,36.99 51.42,36.67 46.66,36.67 46.18,37.15 41.96,37.15 40.87,36.06 38.24,36.06 37.26,35.09 v1(37.11,35.09)
  BOTTOM w0.121: U33.3 36.44,34.11 36.68,34.35 36.68,34.66 v1(37.11,35.09)
EEPROM_WP: length 35.8
  TOP w0.121: U12.10 v1(32,70.86)
  BOTTOM w0.121: R103.2 60.63,78.19 61.01,77.81 61.01,77.1 60.48,76.57 59.44,76.57 58.78,77.23 53.09,77.23 52.58,76.72 50.95,76.72 49.84,75.6 49.84,73.98 46.13,70.27 35.26,70.27 34.67,70.86 v1(32,70.86)
ETHERNET_LED2: length 88.9
  TOP w0.121: J4.17 70.6,76.05 70.18,76.47 v1(68.3,76.47)
  LYR3 w0.121: v1(49.99,72.94) 49.99,72 44.15,66.15 44.15,52.46 36.32,44.64 36.32,42.3 35.21,41.18 35.21,31.59 39.72,27.08 39.72,25.35 40.41,24.65 40.41,22.41 39.83,21.83 39.83,20.41 v1(40.08,20.15)
  LYR6 w0.121: v1(68.3,76.47) 67.69,77.08 63.94,77.08 63.3,76.44 53.98,76.44 50.47,72.94 v1(49.99,72.94)
  BOTTOM w0.121: v1(40.08,20.15) 40.08,19.49 39.09,18.5 37.41,18.5 R155.1
ETHERNET_LED3: length 90
  TOP w0.121: J4.15 v1(71,75.2)
  LYR3 w0.121: v1(50.45,73.65) 50.45,72.02 44.4,65.98 44.4,52.26 36.63,44.49 36.63,42.25 35.49,41.11 35.49,31.66 40.13,27.01 40.13,25.31 40.69,24.75 40.69,22.29 40.44,22.03 40.44,20.54 v1(40.82,20.15)
  LYR6 w0.121: v1(50.45,73.65) 50.83,73.65 53.88,76.69 63.2,76.69 63.83,77.33 68.05,77.33 69.8,75.58 70.62,75.58 v1(71,75.2)
  BOTTOM w0.121: R160.1 39.61,17.98 40.82,19.19 v1(40.82,20.15)
ETHERNET_PAIR0_N: length 83.8
  TOP w0.095: v1(70.89,62.46) 71.11,62.46 71.23,62.57 71.68,62.57 72.14,63.03 72.14,72.05 72.2,72.11 J4.10
  BOTTOM w0.095: T1.3 15.92,38.06 15.83,38.15 15.44,38.15 15.34,38.25 15.34,38.44 15.44,38.54 15.83,38.54 15.92,38.63 15.92,38.84 16.03,38.95 U29.9 U29.2 16.03,40.78 15.91,40.89 15.91,41.24 16.04,41.37 16.04,41.72 15.91,41.85 15.91,42.21 16.04,42.33 16.04,42.69 15.91,42.82 15.91,43.53 16.98,44.59 17.33,44.59 17.46,44.47 17.81,44.47 17.94,44.59 18.3,44.59 18.42,44.47 18.78,44.47 18.91,44.59 24.81,44.59 33,52.78 33,53.18 34.24,54.42 37.71,54.42 44.9,61.61 54.31,61.61 57.48,64.78 62.68,64.78 64.89,62.57 70.56,62.57 70.68,62.46 v1(70.89,62.46)
ETHERNET_PAIR0_P: length 83.9
  TOP w0.095: v1(70.89,62.97) 71.11,62.97 71.23,62.85 71.57,62.85 71.86,63.15 71.86,63.5 71.74,63.63 71.74,63.99 71.86,64.11 71.86,64.47 71.74,64.6 71.74,64.95 71.86,65.08 71.86,65.43 71.74,65.56 71.74,65.92 71.86,66.04 71.86,66.64 71.74,66.76 71.74,67.12 71.86,67.25 71.86,72.05 71.8,72.11 J4.12
  BOTTOM w0.095: v1(70.89,62.97) 70.68,62.97 70.56,62.85 65,62.85 62.79,65.06 57.37,65.06 54.19,61.89 44.78,61.89 37.59,54.7 34.12,54.7 32.72,53.29 32.72,52.9 24.7,44.87 16.86,44.87 15.64,43.65 15.64,40.89 15.53,40.78 U29.1 U29.10 15.52,39.35 15.52,39.01 15.2,38.7 14.58,38.7 13.92,38.03 T1.1
ETHERNET_PAIR1_N: length 85
  TOP w0.095: J4.6 73,72.11 73.06,72.05 73.06,63.04 72.67,62.65 72.67,61.99 72.93,61.73 73.18,61.73 73.29,61.62 v1(73.51,61.62)
  BOTTOM w0.095: T1.6 18.92,38.17 18.47,38.62 17.75,38.62 17.53,38.85 U29.6 U29.5 17.53,40.78 17.42,40.89 17.42,41.24 17.54,41.37 17.54,41.72 17.42,41.85 17.42,42.27 17.54,42.39 17.54,42.75 17.42,42.88 17.42,43.23 17.81,43.62 18.16,43.62 18.29,43.5 18.65,43.5 18.77,43.62 19.43,43.62 19.56,43.5 19.92,43.5 20.04,43.62 25.58,43.62 34.83,52.87 37.51,52.87 45.43,60.79 54.55,60.79 57.85,64.1 61.91,64.1 64.28,61.73 73.18,61.73 73.29,61.62 v1(73.51,61.62)
ETHERNET_PAIR1_P: length 85
  TOP w0.095: v1(73.51,62.13) 73.29,62.13 73.18,62.01 73.04,62.01 72.95,62.11 72.95,62.53 73.34,62.92 73.34,63.64 73.47,63.77 73.47,64.12 73.34,64.25 73.34,64.6 73.47,64.73 73.47,65.09 73.34,65.21 73.34,65.57 73.47,65.7 73.47,66.05 73.34,66.18 73.34,66.59 73.47,66.71 73.47,67.07 73.34,67.19 73.34,72.05 73.4,72.11 J4.4
  BOTTOM w0.095: v1(73.51,62.13) 73.29,62.13 73.18,62.01 64.39,62.01 62.03,64.38 57.74,64.38 54.43,61.07 45.32,61.07 37.39,53.15 34.71,53.15 25.46,43.9 17.69,43.9 17.14,43.35 17.14,40.89 17.03,40.78 U29.4 U29.7 17.03,38.95 16.92,38.85 16.92,38.68 17.02,38.58 17.4,38.58 17.49,38.48 17.49,38.29 17.4,38.2 17.02,38.2 16.92,38.1 T1.4
ETHERNET_PAIR2_N: length 84.3
  TOP w0.095: J4.9 72.2,75.19 72.14,75.13 72.14,74.58 72.8,73.93 73.87,73.93 74.53,73.27 74.53,61.47 73.91,60.84 73.11,60.84 72.99,60.73 v1(72.77,60.73)
  BOTTOM w0.095: v1(72.77,60.73) 72.56,60.73 72.44,60.84 71.91,60.84 71.5,60.43 71.5,58.23 70.53,57.26 43.77,57.26 38.54,52.03 35.36,52.03 26.67,43.34 26.67,43.16 26.42,42.91 26.24,42.91 25.99,42.66 25.17,42.66 25.05,42.53 24.69,42.53 24.56,42.66 24.21,42.66 24.08,42.53 23.73,42.53 23.6,42.66 23.24,42.66 23.12,42.53 22.76,42.53 22.63,42.66 22.28,42.66 21.88,42.26 21.88,41.04 21.99,40.93 U30.2 U30.9 21.99,39.1 21.92,39.02 21.92,38.71 21.83,38.61 21.43,38.61 21.34,38.52 21.34,38.33 21.43,38.23 21.83,38.23 21.92,38.14 T1.9
ETHERNET_PAIR2_P: length 84.4
  TOP w0.095: J4.11 71.8,75.19 71.86,75.13 71.86,74.47 72.68,73.65 73.75,73.65 74.25,73.15 74.25,66.33 74.12,66.2 74.12,65.85 74.25,65.72 74.25,65.37 74.12,65.24 74.12,64.88 74.25,64.76 74.25,64.4 74.12,64.27 74.12,63.92 74.25,63.79 74.25,62.65 74.12,62.52 74.12,62.17 74.25,62.04 74.25,61.58 73.79,61.12 73.11,61.12 72.99,61.24 v1(72.77,61.24)
  BOTTOM w0.095: v1(72.77,61.24) 72.56,61.24 72.44,61.12 71.79,61.12 71.22,60.55 71.22,58.35 70.41,57.54 43.65,57.54 38.42,52.31 35.24,52.31 25.87,42.94 22.16,42.94 21.6,42.38 21.6,41.04 21.49,40.93 U30.1 U30.10 21.49,39.07 21.07,38.65 20.42,38.65 19.92,38.14 T1.7
ETHERNET_PAIR3_N: length 86.2
  TOP w0.095: v1(77.19,59.71) 76.98,59.71 76.86,59.83 75.83,59.83 75.34,60.32 75.34,73.38 74.21,74.51 73.32,74.51 73.06,74.77 73.06,75.13 73,75.19 J4.5
  BOTTOM w0.095: v1(77.19,59.71) 76.98,59.71 76.86,59.83 74.35,59.83 70.89,56.37 44.17,56.37 38.92,51.12 35.89,51.12 27.78,43.01 27.78,42.83 27.53,42.58 27.35,42.58 27.1,42.33 27.1,42.15 26.85,41.89 26.67,41.89 26.42,41.64 25.68,41.64 25.55,41.52 25.2,41.52 25.07,41.64 24.64,41.64 24.51,41.52 24.16,41.52 24.03,41.64 23.68,41.64 23.38,41.35 23.38,41.04 23.49,40.93 U30.5 U30.6 23.49,39.05 23.84,38.7 23.84,38.7 24.74,38.7 24.92,38.52 T1.12
ETHERNET_PAIR3_P: length 86.1
  TOP w0.095: v1(77.19,60.22) 76.98,60.22 76.86,60.11 75.95,60.11 75.62,60.44 75.62,60.79 75.75,60.92 75.75,61.28 75.62,61.4 75.62,61.94 75.75,62.06 75.75,62.42 75.62,62.55 75.62,63.13 75.75,63.26 75.75,63.61 75.62,63.74 75.62,64.15 75.75,64.27 75.75,64.63 75.62,64.76 75.62,73.49 74.33,74.79 73.44,74.79 73.34,74.88 73.34,75.13 73.4,75.19 J4.3
  BOTTOM w0.095: T1.10 22.91,37.31 22.91,38.22 23.01,38.31 23.43,38.31 23.56,38.45 23.56,38.58 23.43,38.72 23.01,38.72 22.91,38.81 22.91,39 22.99,39.08 U30.7 U30.4 22.99,40.93 23.1,41.04 23.1,41.47 23.56,41.92 26.3,41.92 35.78,51.4 38.8,51.4 44.06,56.65 70.78,56.65 74.23,60.11 76.86,60.11 76.98,60.22 v1(77.19,60.22)
ETHERNET_RX_N: length 17
  TOP w0.095: v1(47.55,20.12) 47.67,20.23 48.13,20.23 48.44,20.55 48.44,21.6 48.55,21.71 U11.7 U11.4 48.55,23.53 48.44,23.64 48.44,24.32 48.67,24.55 48.67,25.93 48.82,26.08 48.83,26.08 R80.2 48.73,26.53 48.73,27.14 48.84,27.25 U4.53
  LYR3 w0.102: v1(47.55,20.12) 47.65,20.22 48.02,20.22 48.21,20.03 48.21,19.57 47.63,18.99 47.63,17.31 48.14,16.8 49.38,16.8 49.5,16.62 49.44,16.31 48.14,15.44 J10.3
ETHERNET_RX_P: length 17.1
  TOP w0.095: v1(47.55,20.63) 47.67,20.51 48.01,20.51 48.16,20.66 48.16,20.89 48.06,20.98 47.93,20.98 47.83,21.08 47.83,21.27 47.93,21.37 48.06,21.37 48.16,21.46 48.16,21.6 48.05,21.71 U11.6 U11.5 48.05,23.53 48.16,23.64 48.16,24.43 48.39,24.66 48.39,25.91 48.04,26.25 R81.2 48.45,26.67 48.45,27.14 48.34,27.25 U4.52
  LYR3 w0.102: J10.6 49.84,16.93 49.63,16.97 49.54,17.11 48.26,17.11 47.93,17.44 47.93,18.86 48.52,19.44 48.52,20.15 48.14,20.53 47.65,20.53 v1(47.55,20.63)
ETHERNET_TX_N: length 15.7
  TOP w0.095: J10.1 45.72,16.58 45.84,16.62 45.85,16.62 45.92,16.58 45.97,16.53 47.17,16.53 48.01,17.37 48.01,18.64 49.94,20.57 49.94,21.6 50.05,21.71 U11.10 U11.1 50.05,23.53 49.94,23.64 49.94,24.64 50.32,25.02 50.32,25.9 50.5,26.08 50.5,26.08 R78.2 50.23,26.7 50.23,27.14 50.34,27.25 U4.56
ETHERNET_TX_P: length 15.6
  TOP w0.095: J10.2 45.75,17.83 45.56,17.45 45.72,17 46.09,16.81 46.09,16.81 47.06,16.81 47.73,17.49 47.73,18.76 49.66,20.69 49.66,21.6 49.55,21.71 U11.9 U11.2 49.55,23.53 49.66,23.64 49.66,24.75 50.04,25.13 50.04,25.9 49.88,26.06 49.88,26.06 R79.2 49.95,26.52 49.95,27.14 49.84,27.25 U4.55
EXT_IN1: length 13.5
  BOTTOM w0.381: J20.3 93.03,17.94 85.89,10.8 J21.7
EXT_IN2: length 15.1
  BOTTOM w0.381: J21.9 88.71,12.21 93.3,16.8 99.11,16.8 99.64,17.32 J20.4
EXT_OUT1: length 22.5
  BOTTOM w0.381: J20.5 92.51,20.48 85.6,13.57 83.77,13.57 82.63,12.43 82.63,9.11 84.43,7.3 J21.8
EXT_OUT2: length 28
  BOTTOM w0.381: J21.10 86.85,9.16 84.15,9.16 83.37,9.94 83.37,11.59 84.23,12.46 86.06,12.46 92.94,19.34 97.34,19.34 98.48,20.48 J20.6
EXT_RS232_1_RX: length 6.9
  TOP w0.508: J21.13 96.33,12.69 99.01,15.38 J23.1
EXT_RS232_1_TX: length 8.1
  TOP w0.508: J23.2 104.09,15.38 100.14,11.42 J21.15
EXT_RS232_2_RX: length 14.4
  TOP w0.508: J23.3 98.93,17.92 94.67,13.65 94.67,8.96 J21.14
EXT_RS232_2_TX: length 15
  TOP w0.508: J21.16 98.33,9.11 98.33,11.06 105.18,17.92 J23.4
EXT_RS485_1_A: length 42.6
  TOP w0.381: J23.8 103.18,23 101.91,21.73 99.37,21.73 98.86,22.24 94.24,22.24 92.76,20.76 92.76,16.53 88.72,12.5 80.56,12.5 79.18,11.12 79.18,9.87 78.36,9.05 75.22,9.05 J21.1
EXT_RS485_1_B: length 30.5
  TOP w0.381: J23.7 93.56,23 91.75,21.18 91.75,16.96 88.3,13.51 80.38,13.51 77.67,10.8 J21.3
EXT_RS485_2_A: length 47.9
  TOP w0.381: J23.10 103.51,25.54 102.24,24.27 93.39,24.27 90.73,21.61 90.73,17.38 87.88,14.53 80.18,14.53 78.03,12.38 71.99,12.38 71.61,12 71.61,9.16 J21.2
EXT_RS485_2_B: length 50.9
  TOP w0.381: J21.4 75.5,5.52 72.39,5.52 70.49,7.43 70.49,12.31 71.61,13.42 77.75,13.42 79.87,15.54 87.46,15.54 89.72,17.8 89.72,22.03 93.23,25.54 J23.9
EXT_VCC_9_36V: length 17.9
  TOP w0.305: R3.1 101.28,35.18 C2.1 96.93,37.15 D3.2
  TOP w0.381: R2.1 107.01,36.74 Q2.2 105.95,35.76 105.95,35.02 104.6,33.67 102.8,33.67 102.33,34.13 R3.1
  vias: v1(96.9,41.72) v1(96.9,41.26) v1(96.9,40.8) v1(97.36,41.72) v1(97.36,41.26) v1(97.36,40.8)
GLOBAL_EN: length 43.9
  TOP w0.121: v1(51.13,76.11) 54.03,76.11 54.2,75.94 J4.99
  BOTTOM w0.121: v1(51.13,76.11) 50.18,75.16 50.18,73.97 46.17,69.96 35.16,69.96 33.48,68.29 32.69,68.29 30.81,70.17 22.05,70.17 18.85,73.37 18.85,73.77 18.58,74.04 U18.4
HDMI0_5V:
  vias: v1(97.18,48.02) v1(97.18,47.59) v1(97.61,48.02) v1(97.61,47.59)
HDMI0_CEC: length 58.8
  TOP w0.121: v1(65.48,53.58) 65.48,53.48 65.59,53.38 65.59,45.22 63.8,43.44 J5.151 ; U10.1 U10.10 103.06,47.17 103.02,47.14 v1(103.02,46.85) 103.1,46.77 103.1,43.81 J9.13
  BOTTOM w0.121: v1(103.02,46.85) 103.02,47.21 101.6,48.63 98.1,48.63 93.14,53.58 v1(65.48,53.58)
HDMI0_CLK_N: length 77.3
  TOP w0.095: J5.190 56.2,39.31 56.26,39.37 56.26,39.54 55.97,39.83 53.4,39.83 51.39,41.85 51.39,55.57 v1(51.27,55.69)
  LYR6 w0.102: v1(104.39,50.38) 104.39,50.6 104.49,50.7 104.49,50.84 104.39,50.95 103.22,50.95 103.1,50.82 102.74,50.82 102.61,50.95 102.26,50.95 102.13,50.82 101.77,50.82 101.65,50.95 101.29,50.95 101.17,50.82 100.81,50.82 100.68,50.95 100.33,50.95 100.08,51.2 99.9,51.2 99.64,51.45 99.64,51.63 97.23,54.04 51.82,54.04 51.37,54.48 51.37,55.59 v1(51.27,55.69)
HDMI0_CLK_N1: length 9.6
  BOTTOM w0.095: L22.4 104.39,49.81 U9.6 U9.5 104.39,47.98 104.5,47.87 104.5,47.68 103.86,47.04 103.86,46.65 103.53,46.32 103.53,44.52 103.95,44.11 104.85,44.11 104.96,44 104.96,43.86 104.55,43.44 J9.12
HDMI0_CLK_P: length 77.3
  TOP w0.095: v1(51.78,55.69) 51.67,55.57 51.67,41.96 53.52,40.11 56.09,40.11 56.54,39.65 56.54,39.37 56.6,39.31 J5.188
  LYR6 w0.102: v1(51.78,55.69) 51.68,55.59 51.68,54.61 51.95,54.34 52.23,54.34 52.36,54.47 52.71,54.47 52.84,54.34 53.2,54.34 53.32,54.47 53.68,54.47 53.81,54.34 54.38,54.34 54.51,54.47 54.87,54.47 54.99,54.34 55.35,54.34 55.48,54.47 55.83,54.47 55.96,54.34 97.36,54.34 100.45,51.25 104.51,51.25 104.79,50.97 104.79,50.7 104.89,50.6 v1(104.89,50.38)
HDMI0_CLK_P1: length 11.6
  BOTTOM w0.095: J9.10 105.7,43.38 105.24,43.84 105.24,44.11 104.97,44.39 104.07,44.39 103.81,44.64 103.81,44.82 103.89,44.9 104.32,44.9 104.39,44.97 104.39,45.14 104.3,45.23 103.93,45.23 103.83,45.33 103.83,45.46 103.93,45.56 104.32,45.56 104.42,45.65 104.42,45.79 104.32,45.88 103.91,45.88 103.81,45.99 103.81,46.2 104.14,46.53 104.14,46.93 104.78,47.56 104.78,47.84 104.89,47.95 U9.4 U9.7 104.89,49.81 L22.1
HDMI0_HOTPLUG: length 54.9
  TOP w0.121: v1(102.42,46.77) 102.56,46.91 U10.9 U10.2 ; J5.153 63.4,43.39 65.15,45.14 65.15,50.3 v1(65.08,50.38)
  LYR6 w0.121: v1(102.42,46.77) 102.42,47 102.06,47.36 99.29,47.36 97.89,48.75 95.76,48.75 93.65,50.86 65.56,50.86 v1(65.08,50.38)
  BOTTOM w0.121: v1(102.42,46.77) 102.42,44.85 J9.19
HDMI0_SCL: length 67.6
  TOP w0.121: U10.5 U10.6 ; U10.6 101.06,46.79 102.81,45.04 102.81,42.95 J9.15 ; U10.6 100.73,47.39 v1(100.36,47.76) ; v1(53.93,39.25) 54.2,38.98 J5.200
  LYR3 w0.121: v1(53.93,39.25) 53.22,39.97 v1(53.22,50.05)
  LYR6 w0.121: v1(100.36,47.76) 99.24,47.76 98,49 95.86,49 93.75,51.11 65.25,51.11 64.95,50.81 60.25,50.81 59.49,50.05 v1(53.22,50.05)
HDMI0_SDA: length 69.3
  TOP w0.121: v1(101.56,46.85) U10.7 U10.4 ; v1(53.88,42.4) 53.9,42.4 54.2,42.1 J5.199
  LYR3 w0.121: v1(53.72,49.62) 53.88,49.47 v1(53.88,42.4)
  LYR6 w0.121: v1(101.56,46.85) 101.32,47.08 99.21,47.08 97.79,48.5 95.66,48.5 93.55,50.61 66.17,50.61 65.51,49.95 64.85,49.95 64.32,50.48 60.51,50.48 59.64,49.62 v1(53.72,49.62)
  BOTTOM w0.121: J9.16 102.24,41.59 101.83,41.19 100.74,41.19 99.75,42.18 99.75,43.42 100.18,43.85 100.97,43.85 101.96,44.84 101.96,46.44 v1(101.56,46.85)
HDMI0_TX0_N: length 73.7
  TOP w0.095: v1(52.42,51.04) 52.53,50.93 52.53,41.97 53.86,40.64 56.78,40.64 57.46,39.96 57.46,39.37 57.4,39.31 J5.184
  LYR6 w0.102: v1(105.88,50.38) 105.88,50.16 105.99,50.06 105.99,49.92 105.88,49.82 105.53,49.82 105.4,49.94 105.05,49.94 104.92,49.82 104.29,49.82 104.17,49.94 103.81,49.94 103.69,49.82 103.33,49.82 103.2,49.94 102.85,49.94 102.72,49.82 101.75,49.82 101.63,49.94 101.27,49.94 101.15,49.82 100.29,49.82 97.06,53.05 52.97,53.05 52.52,52.6 52.52,51.14 v1(52.42,51.04)
HDMI0_TX0_N1: length 8.1
  BOTTOM w0.095: J9.9 106.58,43.24 106.58,43.65 105.06,45.17 105.06,46.8 105.99,47.73 105.99,47.87 105.89,47.97 U9.2 U9.9 105.89,49.85 L21.4
HDMI0_TX0_P: length 73.7
  TOP w0.095: v1(52.92,51.04) 52.81,50.93 52.81,42.09 53.98,40.92 56.9,40.92 57.74,40.08 57.74,39.37 57.8,39.31 J5.182
  LYR6 w0.102: v1(52.92,51.04) 52.82,51.14 52.82,52.47 53.1,52.74 53.45,52.74 53.58,52.62 53.93,52.62 54.06,52.74 54.42,52.74 54.54,52.62 54.9,52.62 55.03,52.74 55.38,52.74 55.51,52.62 55.86,52.62 55.99,52.74 56.35,52.74 56.47,52.62 56.83,52.62 56.96,52.74 96.93,52.74 100.16,49.51 106.01,49.51 106.29,49.79 106.29,50.06 106.39,50.16 v1(106.39,50.38)
HDMI0_TX0_P1: length 10
  BOTTOM w0.095: J9.7 107.29,42.8 106.96,42.8 106.86,42.89 106.86,43.77 105.34,45.29 105.34,45.87 105.43,45.97 105.77,45.97 105.87,46.06 105.87,46.26 105.77,46.35 105.43,46.35 105.34,46.45 105.34,46.68 105.59,46.94 105.73,46.94 105.81,46.85 105.95,46.85 106.08,46.99 106.08,47.12 106,47.21 106,47.34 106.27,47.62 106.27,47.86 106.39,47.98 U9.1 U9.10 106.39,49.85 L21.1
HDMI0_TX1_N: length 68
  TOP w0.095: v1(58.55,37.64) 58.66,37.75 58.66,38.13 58.6,38.19 J5.178
  LYR3 w0.102: v1(58.55,37.64) 58.55,37.86 58.65,37.96 58.65,50.96 v1(58.55,51.06)
  LYR6 w0.102: v1(58.55,51.06) 58.65,51.16 58.65,51.53 59.21,52.08 96.52,52.08 99.9,48.7 103.3,48.7 103.43,48.83 103.79,48.83 103.91,48.7 104.27,48.7 104.4,48.83 104.75,48.83 104.88,48.7 105.67,48.7 105.79,48.83 106.15,48.83 106.28,48.7 106.66,48.7 107.24,49.28 107.24,49.46 107.49,49.72 107.67,49.72 107.92,49.97 107.92,50.62 107.82,50.72 v1(107.82,50.94)
HDMI0_TX1_N1: length 9.7
  BOTTOM w0.095: J9.6 108.01,43.58 106.48,45.11 106.48,46.67 107.93,48.12 107.93,48.48 107.82,48.59 U8.5 U8.6 107.82,50.38 L20.4
HDMI0_TX1_P: length 68
  TOP w0.095: v1(59.06,37.64) 58.94,37.76 58.94,38.13 59,38.19 J5.176
  LYR3 w0.102: v1(59.06,51.06) 58.96,50.96 58.96,37.96 59.06,37.86 v1(59.06,37.64)
  LYR6 w0.102: v1(59.06,51.06) 58.96,51.16 58.96,51.4 59.34,51.78 61.04,51.78 61.17,51.65 61.52,51.65 61.65,51.78 62,51.78 62.13,51.65 62.49,51.65 62.61,51.78 63.07,51.78 63.2,51.65 63.55,51.65 63.68,51.78 64.04,51.78 64.16,51.65 64.52,51.65 64.65,51.78 96.4,51.78 99.77,48.4 106.78,48.4 108.23,49.84 108.23,50.62 108.33,50.72 v1(108.33,50.94)
HDMI0_TX1_P1: length 11.6
  BOTTOM w0.095: J9.4 109.17,43.96 108.84,44.29 107.69,44.29 106.76,45.22 106.76,46.56 107.6,47.4 107.74,47.4 107.98,47.16 108.11,47.16 108.25,47.3 108.25,47.43 108.01,47.67 108.01,47.81 108.21,48 108.21,48.49 108.32,48.6 U8.4 U8.7 108.32,50.38 L20.1
HDMI0_TX2_N: length 72.2
  TOP w0.095: J5.172 59.8,38.19 59.86,38.13 59.86,37.75 v1(59.75,37.64)
  LYR3 w0.102: v1(59.75,55.85) 59.85,55.75 59.85,37.96 59.75,37.86 v1(59.75,37.64)
  LYR6 w0.102: v1(59.75,55.85) 59.85,55.75 59.85,55.26 60.13,54.98 100.21,54.98 103.25,51.93 104.88,51.93 105.01,51.8 105.36,51.8 105.49,51.93 105.84,51.93 105.97,51.8 106.33,51.8 106.45,51.93 106.81,51.93 106.94,51.8 107.29,51.8 107.42,51.93 107.77,51.93 107.9,51.8 108.26,51.8 108.38,51.93 108.89,51.93 109.42,51.4 109.42,51.26 109.31,51.16 v1(109.31,50.94)
HDMI0_TX2_N1: length 8.9
  BOTTOM w0.095: L19.4 109.32,50.38 U8.9 U8.2 109.32,48.53 109.43,48.42 109.43,48.17 111.28,46.32 111.28,44.91 110.18,43.81 110.18,43.38 J9.3
HDMI0_TX2_P: length 72.2
  TOP w0.095: v1(60.26,37.64) 60.14,37.76 60.14,38.13 60.2,38.19 J5.170
  LYR3 w0.102: v1(60.26,37.64) 60.26,37.86 60.16,37.96 60.16,55.75 v1(60.26,55.85)
  LYR6 w0.102: v1(109.82,50.94) 109.82,51.16 109.72,51.26 109.72,51.53 109.01,52.23 103.38,52.23 100.33,55.28 66.73,55.28 66.6,55.41 66.25,55.41 66.12,55.28 65.71,55.28 65.59,55.41 65.23,55.41 65.1,55.28 64.39,55.28 64.26,55.41 63.91,55.41 63.78,55.28 62.82,55.28 62.69,55.41 62.33,55.41 62.21,55.28 60.26,55.28 60.16,55.38 60.16,55.75 v1(60.26,55.85)
HDMI0_TX2_P1: length 10.8
  BOTTOM w0.095: L19.1 109.82,50.38 U8.10 U8.1 109.82,48.54 109.71,48.43 109.71,48.29 111.56,46.43 111.56,46.28 111.65,46.18 111.9,46.18 111.99,46.09 111.99,45.9 111.9,45.8 111.65,45.8 111.56,45.71 111.56,45.51 111.65,45.42 111.9,45.42 111.99,45.32 111.99,45.13 111.9,45.04 111.65,45.04 111.56,44.94 111.56,44.79 111.28,44.51 111.28,44.38 111.45,44.21 111.45,44.07 111.32,43.94 111.18,43.94 111.01,44.11 110.88,44.11 110.46,43.7 110.46,43.38 J9.1
